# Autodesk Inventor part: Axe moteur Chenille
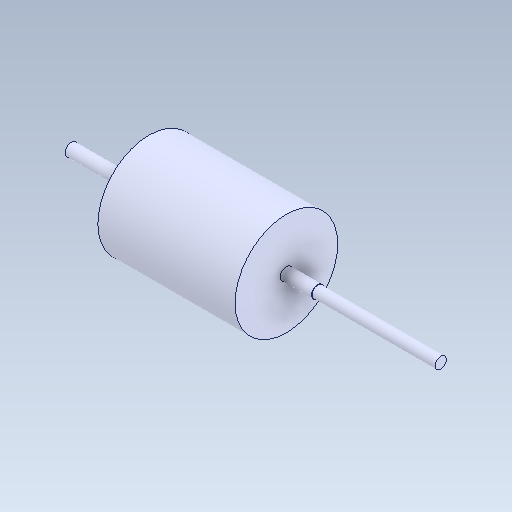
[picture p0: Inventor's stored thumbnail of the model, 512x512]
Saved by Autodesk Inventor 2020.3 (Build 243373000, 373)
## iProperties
Created: 2018-09
Part Number: Axe moteur Chenille
Material: Générique
Document SubType Name: Modeling
Designer: ficho
Density: 1 g/cm^3
Appearance: Par défaut
Mass: 9.68838 g
Surface Area: 28.5614 cm^2
Volume: 9.68838 cm^3
Sending System: SolidWorks 2015
Last Author: adrien
Last Saved: 2019-01-14
Author: ficho
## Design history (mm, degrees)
feature "Enlèvement de matière-Révolution1"
sketch "Esquisse1"
  geometry: C1 r 6.095 at (0, 0); C2 r 1.15 at (0, 0) reference; 1 further point
  constraints: 1 centre point, 1 coincident
extrude "Extrusion1" cut sketch "Esquisse1" stored distance "d0" = 10; taper "d1" = 0 deg
node "Solide1"
